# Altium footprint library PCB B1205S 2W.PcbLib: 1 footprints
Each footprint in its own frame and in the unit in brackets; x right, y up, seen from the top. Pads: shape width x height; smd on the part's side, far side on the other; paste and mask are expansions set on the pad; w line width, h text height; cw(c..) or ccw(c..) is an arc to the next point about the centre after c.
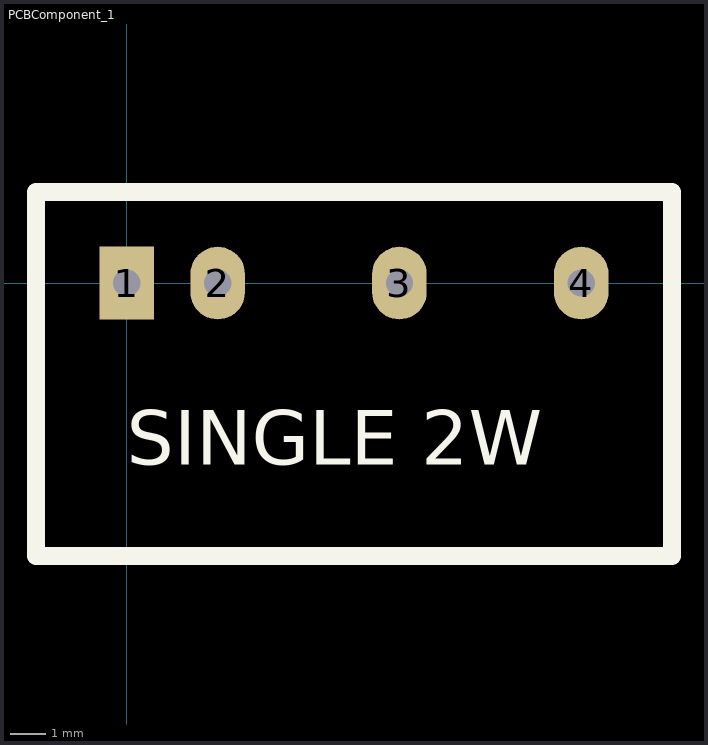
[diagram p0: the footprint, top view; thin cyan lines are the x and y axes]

## PCBComponent_1 [mil]
pads (4):
  rect 60x80 hole 30: 1(0,0)
  oval 60x80 hole 30: 2(100,0) 3(300,0) 4(500,0)
Top Overlay:
  lines w19.68: -100,-300 600,-300 600,100 -100,100 -100,-300
  text "SINGLE 2W" at 0,-200 h60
